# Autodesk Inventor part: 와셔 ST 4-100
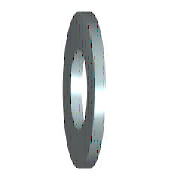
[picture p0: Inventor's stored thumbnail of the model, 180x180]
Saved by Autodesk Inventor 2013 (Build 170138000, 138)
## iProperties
IsCustomPart: 0
Created: 2012-02
Part Number: 와셔 ST 4-100
Material: 강철, 연강
Description: 평면 와셔 - 일반 시리즈 - 제품 등급 C
Document SubType Name: Modeling
Standard: ISO 7091
Designer: mduedu
Standard Revision: Second edition 2000-06-01
Standards Organization: ISO
Language: ko-KR
Size Designation: ST 4 - 100 HV
Categories: <MemberInstance><Categories><Category DisplayName="조임쇠" InternalName="e4da775c-781d-43d5-af7c-5136215cf5a6" Mnemonic="FSTN"><Category DisplayName="와셔" InternalN
Density: 7.86 g/cm^3
Mass: 0.492315 g
Surface Area: 1.70824 cm^2
Volume: 0.0626355 cm^3
Author: mduedu
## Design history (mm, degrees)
sketch "스케치"
  geometry: C1 r 5 at (0, 0); C2 r 2.25 at (0, 0); 1 further point
  constraints: 2 centre point, 2 coincident
  dimensions: "d0" = 4.5 diameter of C2 (= SD1); "d1" = 10 diameter of C1 (= SD2)
extrude "본체" new body sketch "스케치" distance "d2" = 1 (= SD); taper "d3" = 0 deg
workaxis "Work Axis1"
workplane "Work Plane1"
body "Solid1"
other parameters: "SD1" = 4.5 [user parameter; used in 1 equation term], "SD2" = 10 [user parameter; used in 1 equation term], "SD" = 1 [user parameter; used in 1 equation term], "d4" = 0, "d5" = 0, "d6" = 0, "d7" = 0, "NND" = 4 [user parameter]
